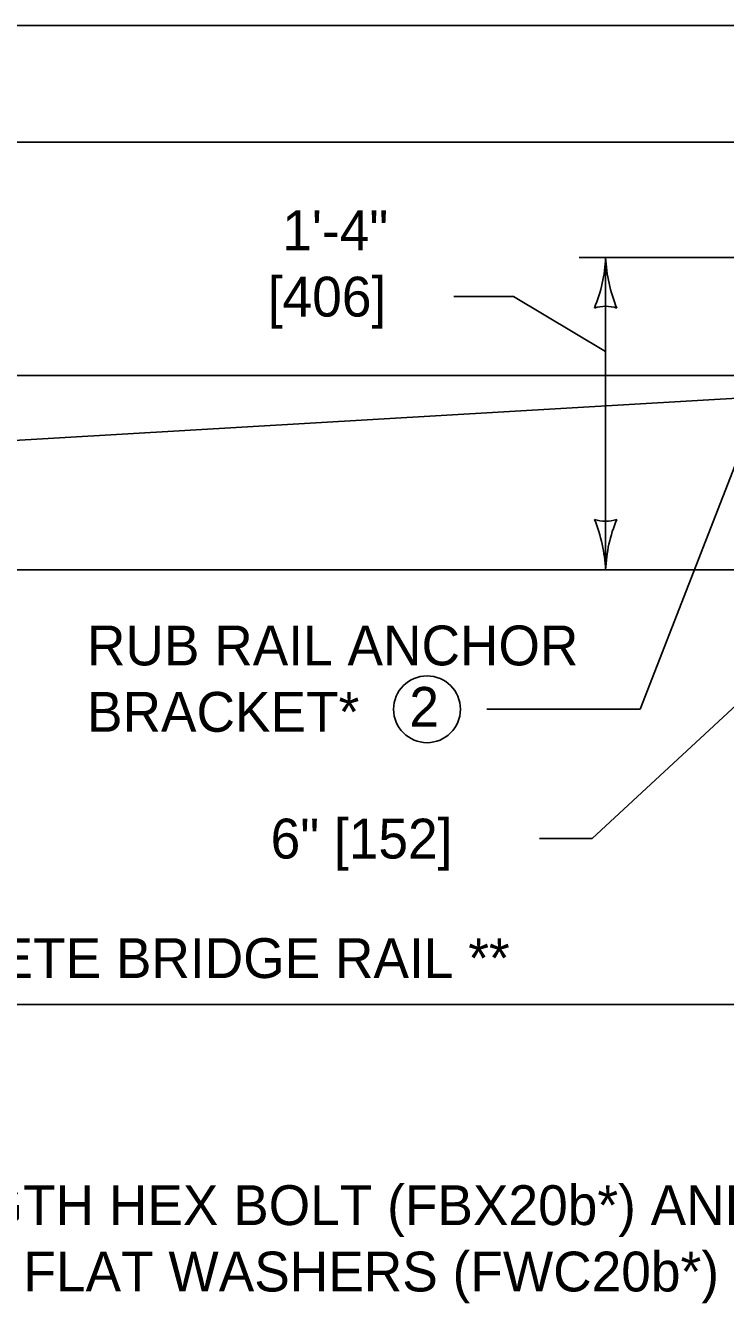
# Model space of a CAD drawing. Extents: x 49983 to 50021, y 49963.5 to 50011.4.
# Drawn here: x 50003.419 to 50004.473, y 49993.361 to 49995.286 of the extents above; entities that cross this region are included whole.
import ezdxf

# ---------------------------------------------------------------- set-up
doc = ezdxf.new("R2010")
doc.units = 0
for name, color, linetype in [('Level 1', 7, 'Continuous'), ('Level 2', 7, 'Continuous'), ('Level 3', 7, 'Continuous'), ('Level 5', 7, 'Continuous')]:
    doc.layers.add(name, color=color, linetype=linetype)

msp = doc.modelspace()

# ---------------------------------------------------------------- linework, layer by layer
at = {"layer": 'Level 1'}
for p, q in [((50005.4515, 49995.2862), (50001.5623, 49995.2862)), ((50005.456, 49995.1105), (50001.5623, 49995.1105)), ((50005.0789, 49994.7591), (50000.7665, 49994.7591)), ((50005.0789, 49994.7591), (50001.565, 49994.5542)), ((50005.1046, 49994.4663), (50000.7665, 49994.4663))]:
    msp.add_line(p, q, dxfattribs=at)
at = {"layer": 'Level 2'}
msp.add_circle((50004.0237, 49994.2564), 0.0503, dxfattribs=at)
at = {"layer": 'Level 3'}
for p, q in [((50004.2927, 49994.9368), (50004.2927, 49994.4663)), ((50004.3445, 49994.2564), (50004.5937, 49994.8968)), ((50004.1542, 49994.8779), (50004.0643, 49994.8779)), ((50004.2927, 49994.7953), (50004.1542, 49994.8779)), ((50004.2722, 49994.0616), (50004.5899, 49994.3564)), ((50004.114, 49994.2564), (50004.3445, 49994.2564)), ((50004.1932, 49994.0616), (50004.2722, 49994.0616)), ((50005.0789, 49993.8116), (50001.5908, 49993.8116))]:
    msp.add_line(p, q, dxfattribs=at)
for centre, radius, start, end in [((50004.0705, 49994.946), 0.2223, 337.456, 357.6395), ((50004.5254, 49994.9483), 0.233, 182.8273, 202.0772), ((50004.2927, 49994.8086), 0.0548, 72.1388, 107.8612), ((50004.2927, 49994.5945), 0.0548, 252.1388, 287.8612), ((50004.06, 49994.4548), 0.233, 2.8273, 22.0772), ((50004.5148, 49994.4572), 0.2223, 157.456, 177.6395)]:
    msp.add_arc(centre, radius, start, end, dxfattribs=at)
at = {"layer": 'Level 5'}
msp.add_line((50005.0462, 49994.9368), (50004.2527, 49994.9368), dxfattribs=at)

# ---------------------------------------------------------------- texts
at = {"layer": 'Level 1'}
msp.add_text('2', height=0.06, dxfattribs=at).set_placement((50003.9971, 49994.23))
at = {"layer": 'Level 2'}
for s, p in [('1\'-4"', (50003.8056, 49994.9479)), ('[406]', (50003.7839, 49994.8479))]:
    msp.add_text(s, height=0.06, rotation=360, dxfattribs=at).set_placement(p)
for s, p in [('RUB RAIL ANCHOR', (50003.5116, 49994.3225)), ('BRACKET* ', (50003.5116, 49994.2225)), ('6" [152]', (50003.7882, 49994.0316)), ('10\'-0" [3.05 m] TAPERED CONCRETE BRIDGE RAIL **', (50002.1426, 49993.8516)), ('3/4" DIA. x 4" [M20 x 102] HIGH STRENGTH HEX BOLT (FBX20b*) AND', (50001.9181, 49993.4795)), ('NUT (FNX20b*) WITH TWO HARDENED FLAT WASHERS (FWC20b*) (TYP.)', (50001.9181, 49993.3795))]:
    msp.add_text(s, height=0.06, dxfattribs=at).set_placement(p)

doc.saveas('drawing.dxf')
